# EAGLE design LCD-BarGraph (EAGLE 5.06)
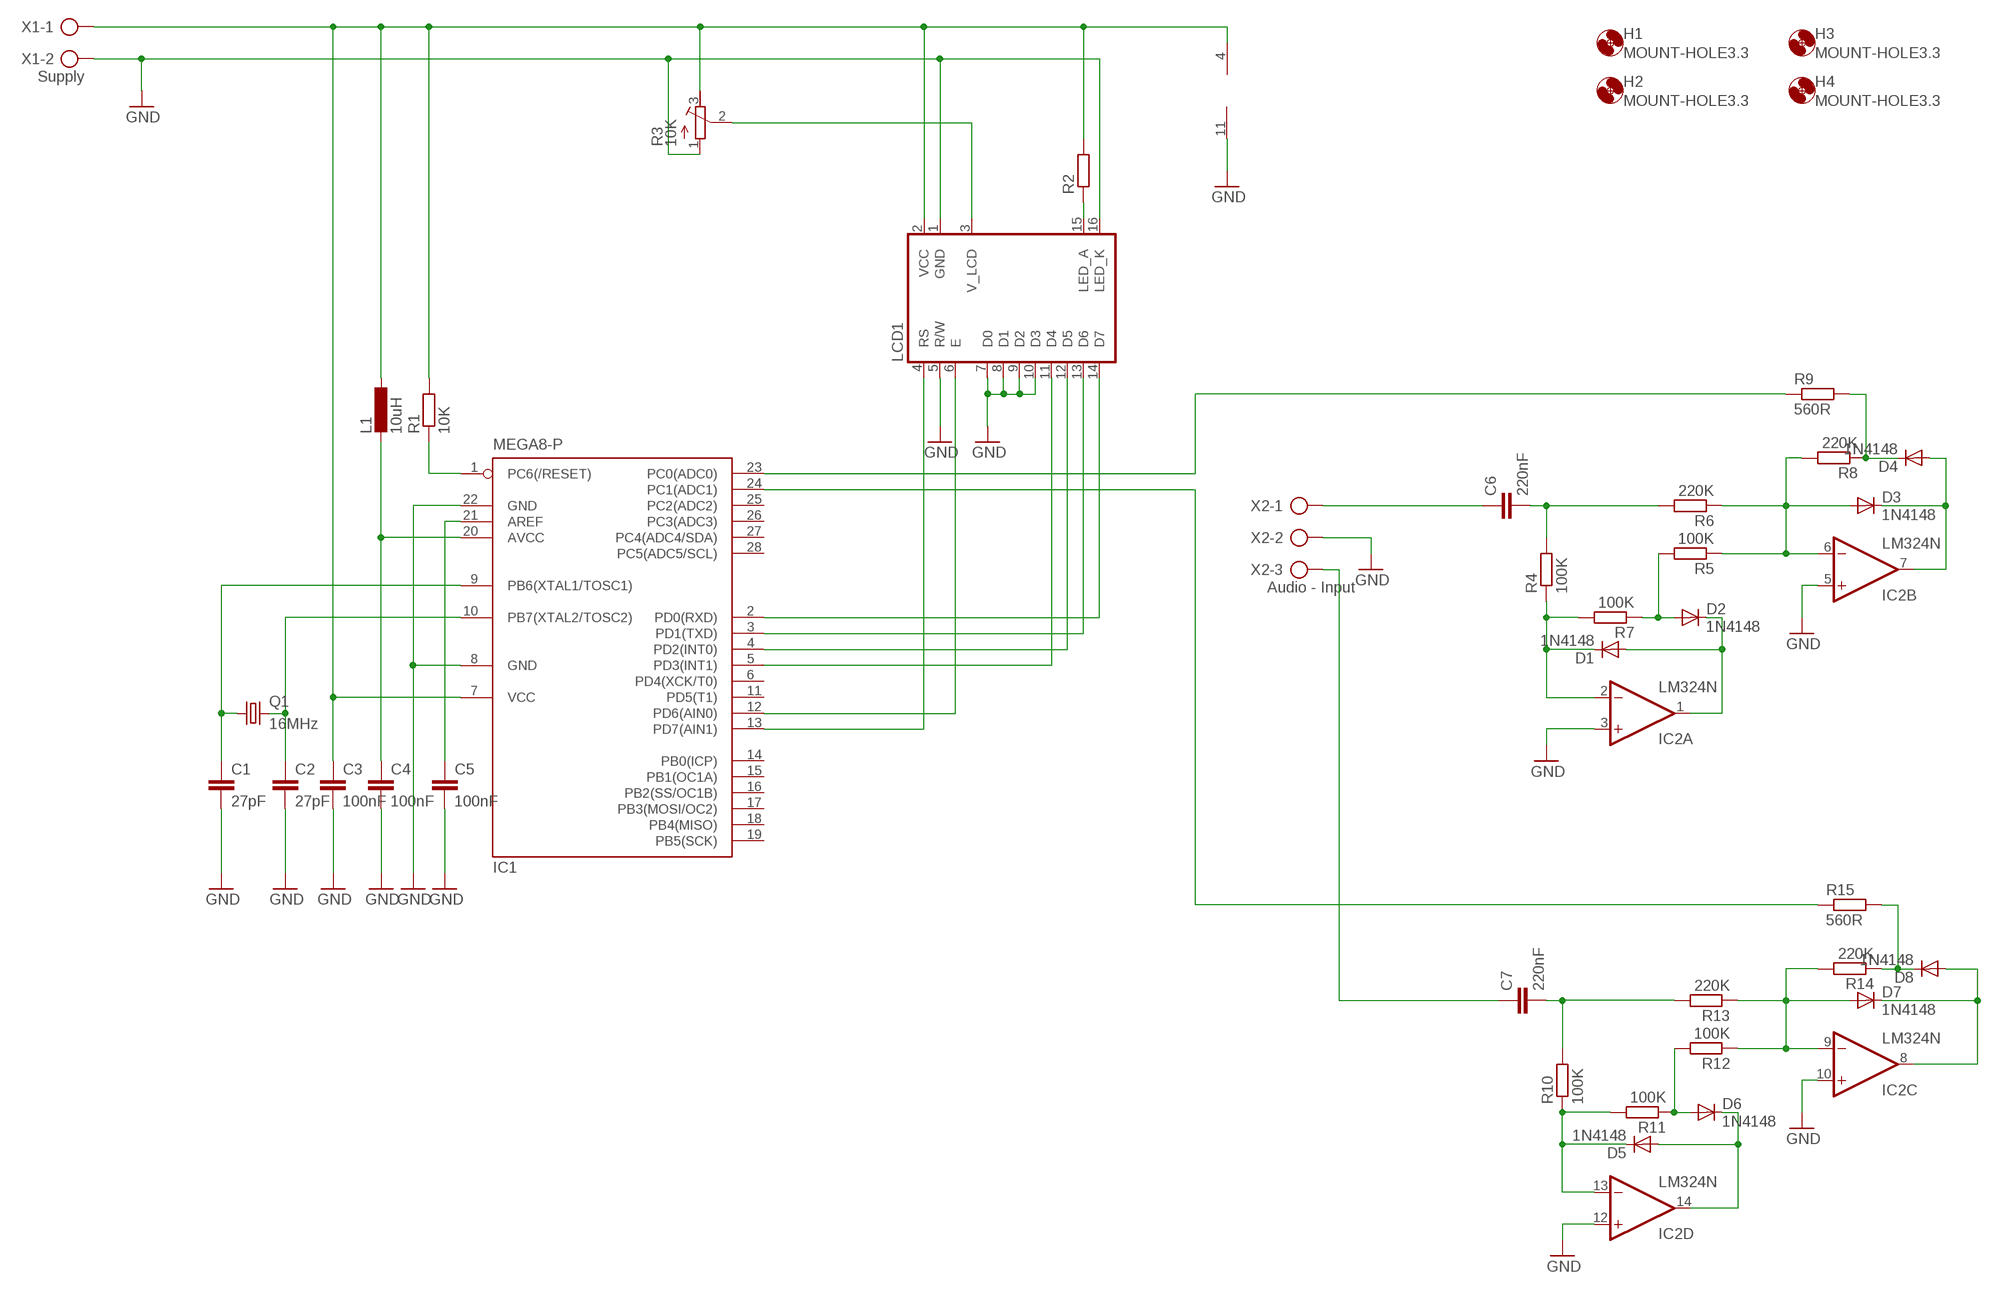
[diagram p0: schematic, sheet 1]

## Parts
C1  27pF  C-EU025-030X050  [C025-030X050]
C2  27pF  C-EU025-030X050  [C025-030X050]
C3  100nF  C-EU025-030X050  [C025-030X050]
C4  100nF  C-EU025-030X050  [C025-030X050]
C5  100nF  C-EU025-030X050  [C025-030X050]
C6  220nF  C-EU025-030X050  [C025-030X050]
C7  220nF  C-EU025-030X050  [C025-030X050]
D1  1N4148  1N4148DO35-7  [DO35-7]
D2  1N4148  1N4148DO35-7  [DO35-7]
D3  1N4148  1N4148DO35-7  [DO35-7]
D4  1N4148  1N4148DO35-7  [DO35-7]
D5  1N4148  1N4148DO35-7  [DO35-7]
D6  1N4148  1N4148DO35-7  [DO35-7]
D7  1N4148  1N4148DO35-7  [DO35-7]
D8  1N4148  1N4148DO35-7  [DO35-7]
H1  MOUNT-HOLE3.3  [3,3]
H2  MOUNT-HOLE3.3  [3,3]
H3  MOUNT-HOLE3.3  [3,3]
H4  MOUNT-HOLE3.3  [3,3]
IC1  MEGA8-P  [DIL28-3]
IC2  LM324N  [DIL14]
L1  10uH  L-MESC  [L-MESC]
LCD1  LCD-4X20  [LCD-4X20]
Q1  16MHz  CRYSTALHC49U-V  [HC49U-V]
R1  10K  R-EU_0207/10  [0207/10]
R2  R-EU_0207/10  [0207/10]
R3  10K  R-TRIMM64X  [RTRIM64X]
R4  100K  R-EU_0207/10  [0207/10]
R5  100K  R-EU_0207/10  [0207/10]
R6  220K  R-EU_0207/10  [0207/10]
R7  100K  R-EU_0207/10  [0207/10]
R8  220K  R-EU_0207/10  [0207/10]
R9  560R  R-EU_0207/10  [0207/10]
R10  100K  R-EU_0207/10  [0207/10]
R11  100K  R-EU_0207/10  [0207/10]
R12  100K  R-EU_0207/10  [0207/10]
R13  220K  R-EU_0207/10  [0207/10]
R14  220K  R-EU_0207/10  [0207/10]
R15  560R  R-EU_0207/10  [0207/10]
X1  Supply  AK300/2  [AK300/2]
X2  Audio - Input  AK300/3  [AK300/3]

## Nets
GND: C1.2 C2.2 C3.2 C4.2 C5.2 IC1.8(GND) IC1.22(GND) IC2.3(A:+IN) IC2.5(B:+IN) IC2.10(C:+IN) IC2.11(P:V-) IC2.12(D:+IN) LCD1.1(GND) LCD1.5(R/W) LCD1.7(D0) LCD1.8(D1) LCD1.9(D2) LCD1.10(D3) LCD1.16(LED_K) R3.1(E) X1.2 X2.2
N$1: C2.1 IC1.10(PB7(XTAL2/TOSC2)) Q1.2
N$2: C1.1 IC1.9(PB6(XTAL1/TOSC1)) Q1.1
N$3: C3.1 IC1.7(VCC) IC2.4(P:V+) L1.1 LCD1.2(VCC) R1.2 R2.2 R3.3(A) X1.1
N$4: C4.1 IC1.20(AVCC) L1.2
N$5: IC1.1(PC6(/RESET)) R1.1
N$6: LCD1.15(LED_A) R2.1
N$7: C5.1 IC1.21(AREF)
N$8: LCD1.3(V_LCD) R3.2(S)
N$9: C6.1 X2.1
N$10: C6.2 R4.2 R6.2
N$11: D1.C IC2.2(A:-IN) R4.1 R7.2
N$12: D1.A D2.C IC2.1(A:OUT)
N$13: D2.A R5.2 R7.1
N$14: D3.A IC2.6(B:-IN) R5.1 R6.1 R8.2
N$15: D3.C D4.A IC2.7(B:OUT)
N$16: D4.C R8.1 R9.2
N$17: C7.1 X2.3
N$18: C7.2 R10.2 R13.2
N$19: D5.C IC2.13(D:-IN) R10.1 R11.2
N$20: D6.A R11.1 R12.2
N$21: D5.A D6.C IC2.14(D:OUT)
N$22: D7.A IC2.9(C:-IN) R12.1 R13.1 R14.2
N$23: D7.C D8.A IC2.8(C:OUT)
N$24: D8.C R14.1 R15.2
N$25: IC1.23(PC0(ADC0)) R9.1
N$26: IC1.5(PD3(INT1)) LCD1.11(D4)
N$27: IC1.24(PC1(ADC1)) R15.1
N$28: IC1.4(PD2(INT0)) LCD1.12(D5)
N$29: IC1.3(PD1(TXD)) LCD1.13(D6)
N$30: IC1.2(PD0(RXD)) LCD1.14(D7)
N$31: IC1.12(PD6(AIN0)) LCD1.6(E)
N$32: IC1.13(PD7(AIN1)) LCD1.4(RS)
Unconnected: IC1.6(PD4(XCK/T0)) IC1.11(PD5(T1)) IC1.14(PB0(ICP)) IC1.15(PB1(OC1A)) IC1.16(PB2(SS/OC1B)) IC1.17(PB3(MOSI/OC2)) IC1.18(PB4(MISO)) IC1.19(PB5(SCK)) IC1.25(PC2(ADC2)) IC1.26(PC3(ADC3)) IC1.27(PC4(ADC4/SDA)) IC1.28(PC5(ADC5/SCL))

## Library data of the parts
C1-C7 = rcl:C-EU: CAPACITOR, European symbol
D1-D8 = diode:1N4148: DIODE
H1-H4 = holes:MOUNT-HOLE: MOUNTING HOLE with drill center marker
IC1 = atmel:MEGA8-P: MICROCONTROLLER 8 Kbytes FLASH, 1 kbytes SRAM, 512 bytes EEPROM, USART, 4-channel 10 bit ADC, 2-channel 8 bit ADC Pin compatible with Atmega48, ATMega88, ATMega168 Source: avr.lbr
IC2 = linear:LM324: OP AMP
L1 = oli:L-MESC: Medium Suppression Coil
LCD1 = oli:LCD-4X20: LCD 4 x 20 Characters
Q1 = crystal:CRYSTAL: CRYSTAL
R1 R2 R4-R15 = resistor:R-EU_: RESISTOR, European symbol
R3 = rcl:R-TRIMM: Trimm resistor
X1 = con-ptr500:AK300/2: CONNECTOR
X2 = con-ptr500:AK300/3: CONNECTOR

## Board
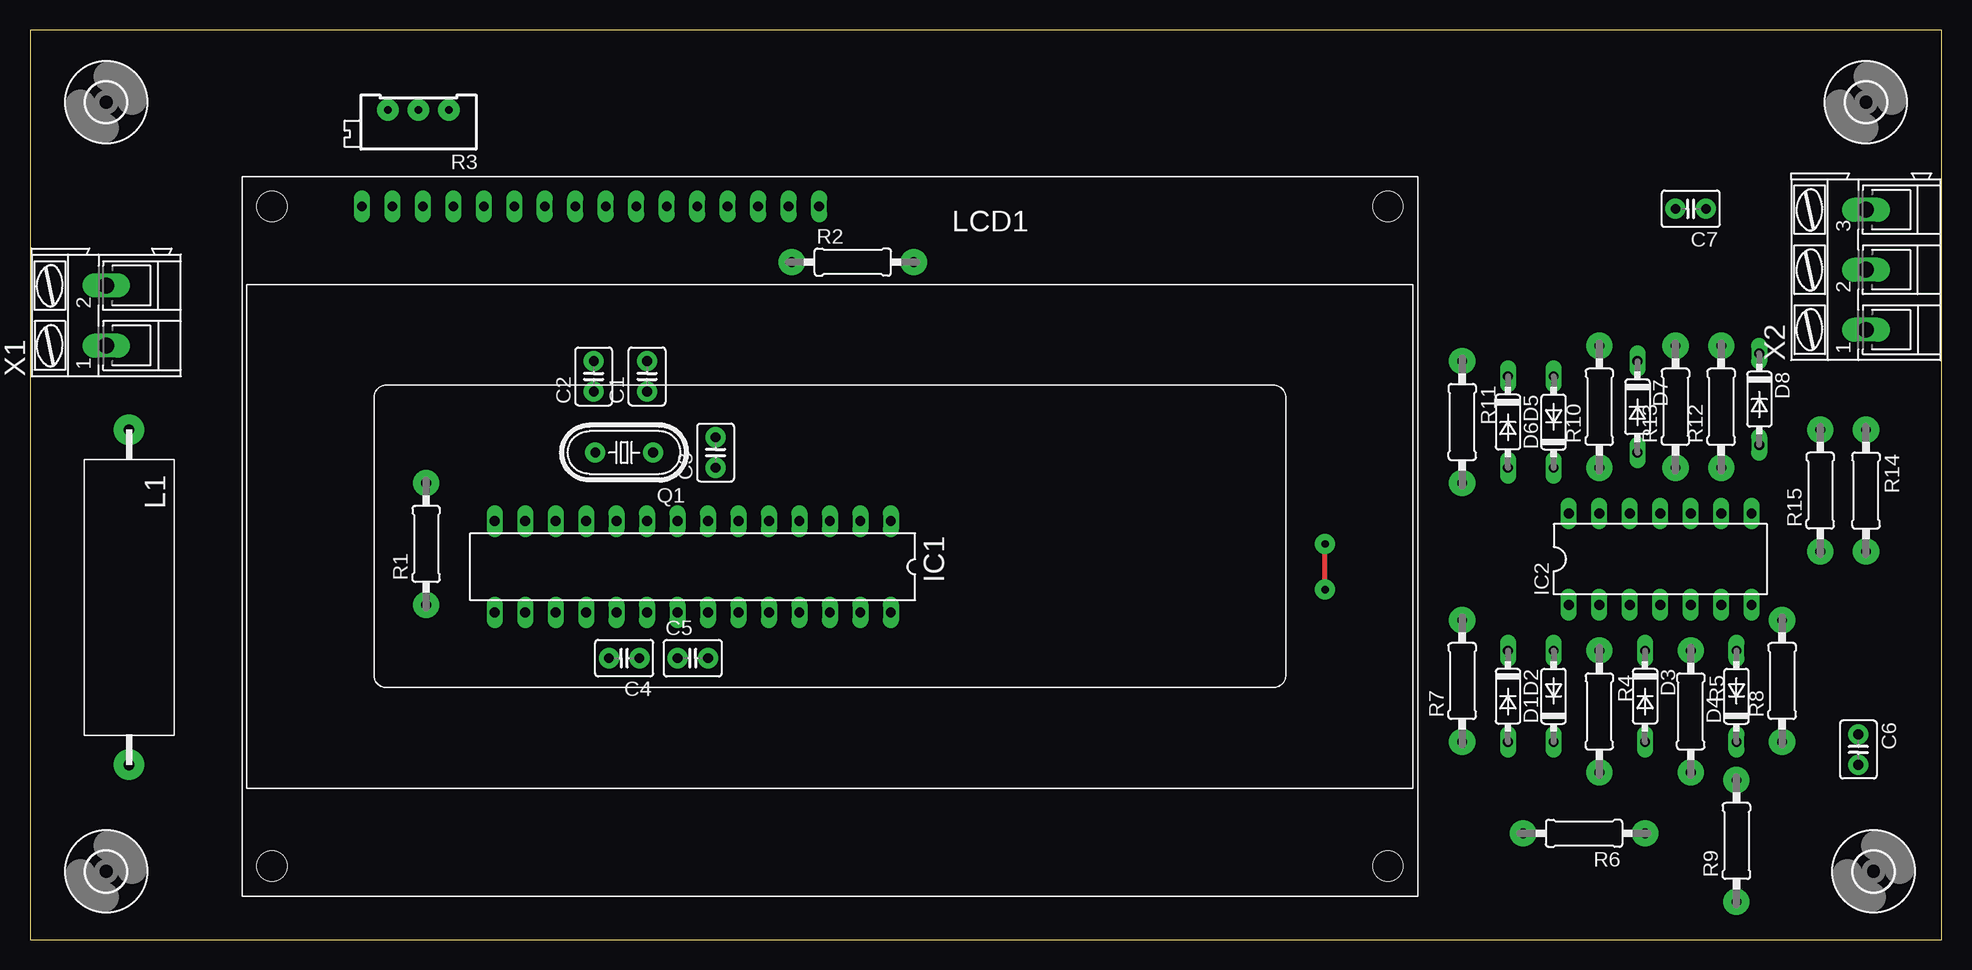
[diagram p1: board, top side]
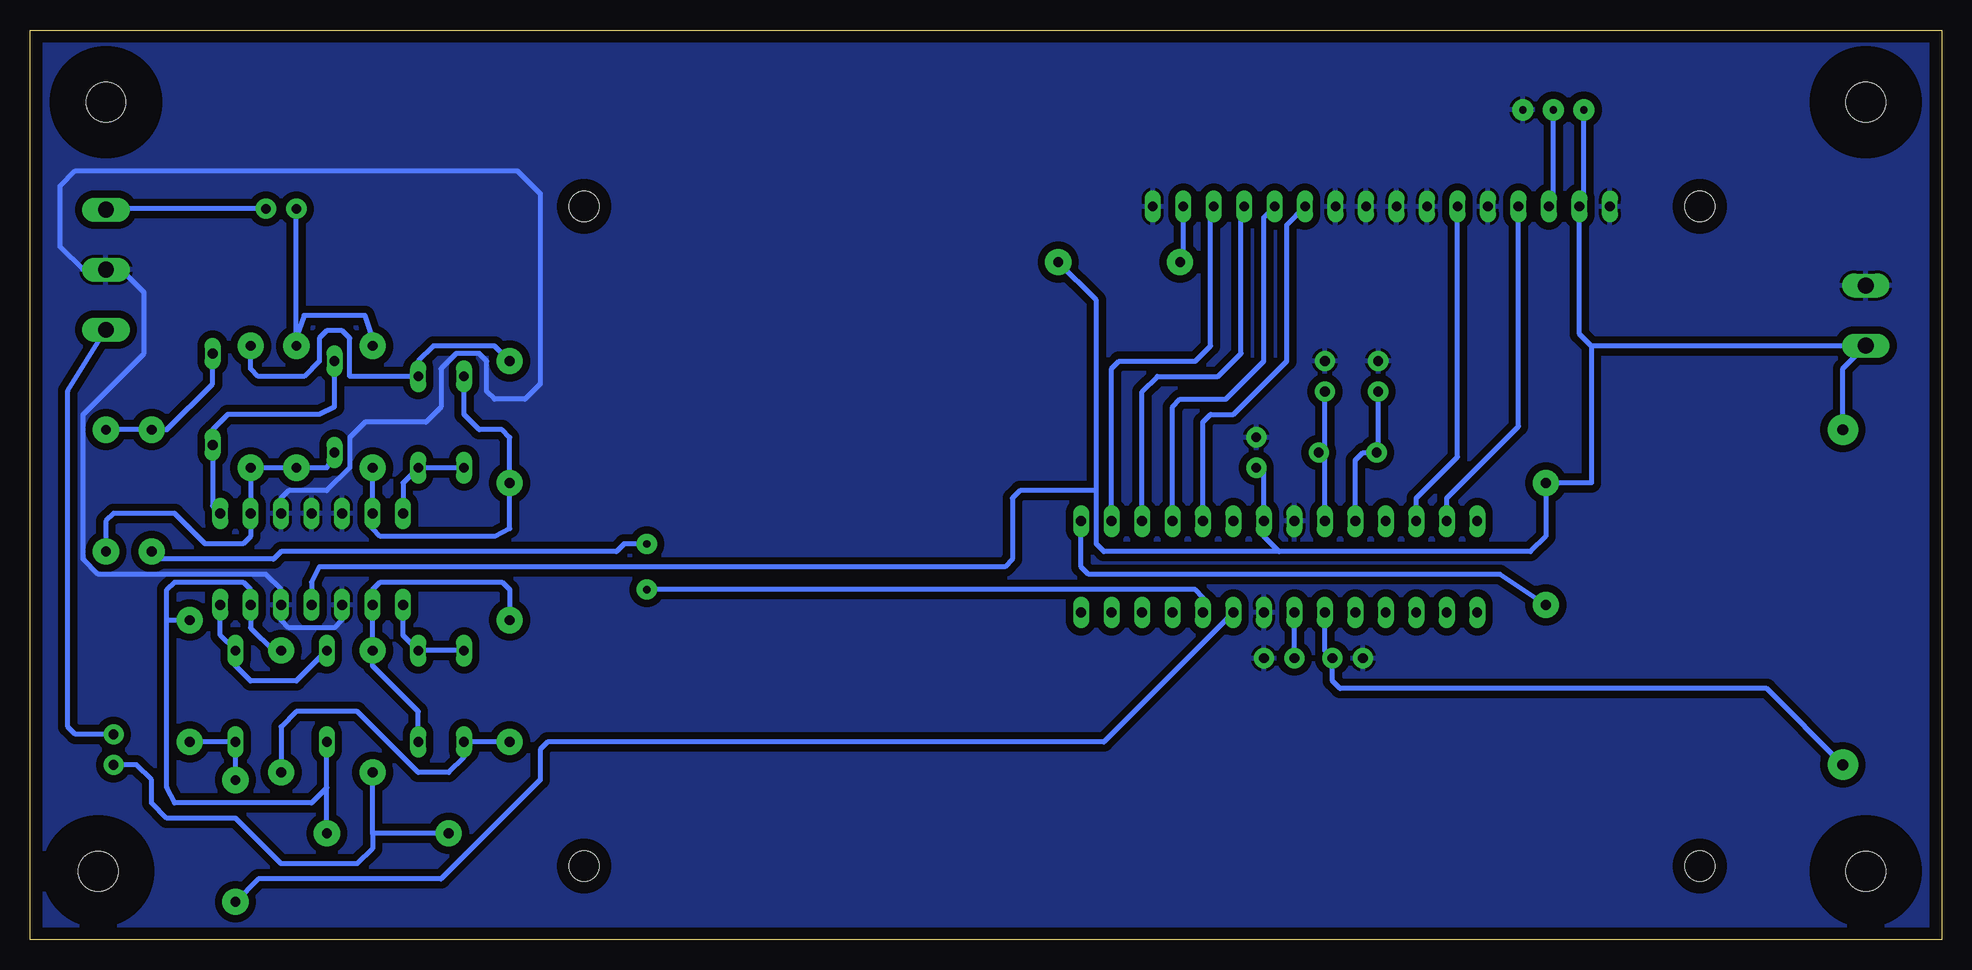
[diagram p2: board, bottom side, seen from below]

Size 159.37 x 75.87 mm. Coordinates in mm from the lower left corner, seen from the top.
Outline: 0,0 159.37,0 159.37,75.87 0,75.87 0,0
Copper layers (1*16): Top 0.035mm / dielectric 1.5mm / Bottom 0.035mm
Design rules "default": minimum track width 10mil, minimum drill 24mil, track to track 8mil, track to pad 8mil, pad to pad 8mil, via to via 8mil, smd to smd 8mil, copper to edge 40mil, drill to drill 8mil, minimum pad ring 10mil, minimum via ring 8mil, stop-mask expansion 4mil, vias tented up to drill 0mil, thermal gap 10mil

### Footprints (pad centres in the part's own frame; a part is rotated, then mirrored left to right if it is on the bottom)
C025-030X050 = drill 0.813 pad 1.676 round: 1 -1.27,0; 2 1.27,0
DO35-7 = drill 0.813 long: A 3.81,0; C -3.81,0
3,3 = hole 3.3: 0,0
DIL28-3 = drill 0.813 long: 1 -16.51,-3.81; 2 -13.97,-3.81; 3 -11.43,-3.81; 4 -8.89,-3.81; 5 -6.35,-3.81; 6 -3.81,-3.81; 7 -1.27,-3.81; 8 1.27,-3.81; 9 3.81,-3.81; 10 6.35,-3.81; 11 8.89,-3.81; 12 11.43,-3.81; 13 13.97,-3.81; 14 16.51,-3.81; 15 16.51,3.81; 16 13.97,3.81; 17 11.43,3.81; 18 8.89,3.81; 19 6.35,3.81; 20 3.81,3.81; 21 1.27,3.81; 22 -1.27,3.81; 23 -3.81,3.81; 24 -6.35,3.81; 25 -8.89,3.81; 26 -11.43,3.81; 27 -13.97,3.81; 28 -16.51,3.81
DIL14 = drill 0.813 long: 1 -7.62,-3.81; 2 -5.08,-3.81; 3 -2.54,-3.81; 4 0,-3.81; 5 2.54,-3.81; 6 5.08,-3.81; 7 7.62,-3.81; 8 7.62,3.81; 9 5.08,3.81; 10 2.54,3.81; 11 0,3.81; 12 -2.54,3.81; 13 -5.08,3.81; 14 -7.62,3.81
L-MESC = drill 0.9 pad 2.54 round: 1 -13.97,0; 2 13.97,0
LCD-4X20 = drill 0.813 long: 1 -39,27.5; 2 -36.46,27.5; 3 -33.92,27.5; 4 -31.38,27.5; 5 -28.84,27.5; 6 -26.3,27.5; 7 -23.76,27.5; 8 -21.22,27.5; 9 -18.68,27.5; 10 -16.14,27.5; 11 -13.6,27.5; 12 -11.06,27.5; 13 -8.52,27.5; 14 -5.98,27.5; 15 -3.44,27.5; 16 -0.9,27.5 | hole 2.5: -46.5,-27.5; -46.5,27.5; 46.5,27.5; 46.5,-27.5
HC49U-V = drill 0.813 pad 1.676 round: 1 -2.413,0; 2 2.413,0
0207/10 = drill 0.813 pad 2.184 round: 1 -5.08,0; 2 5.08,0
RTRIM64X = drill 0.61 pad 1.778 round: 1 1.27,-2.54; 2 1.27,0; 3 1.27,2.54
AK300/2 = drill 1.321 long: 1 -2.515,0; 2 2.489,0
AK300/3 = drill 1.321 long: 1 -5.004,0; 2 0,0; 3 5.004,0

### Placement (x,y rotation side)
C1  51.44,46.99 90 top
C2  46.99,46.99 90 top
C3  57.15,40.64 90 top
C4  49.53,23.5 180 top
C5  55.25,23.5 0 top
C6  152.4,15.88 270 top
C7  138.43,60.96 180 top
D1  127,20.32 90 top
D2  123.19,20.32 270 top
D3  134.62,20.32 270 top
D4  142.24,20.32 90 top
D5  123.19,43.18 270 top
D6  127,43.18 90 top
D7  133.99,44.45 270 top
D8  144.15,45.09 270 top
H1  6.35,5.71 0 top
H2  6.35,69.85 0 top
H3  153.03,69.85 0 top
H4  153.67,5.71 0 top
IC1  55.25,31.11 180 top
IC2  135.89,31.75 0 top
L1  8.25,28.57 270 top
LCD1  66.67,33.66 0 top
Q1  49.53,40.64 180 top
R1  33.02,33.02 90 top
R2  68.58,56.52 0 top
R3  32.39,67.94 90 top
R4  130.81,19.05 270 top
R5  138.43,19.05 270 top
R6  129.54,8.89 180 top
R7  119.38,21.59 90 top
R8  146.05,21.59 90 top
R9  142.24,8.26 90 top
R10  130.81,44.45 90 top
R11  119.38,43.18 270 top
R12  140.97,44.45 90 top
R13  137.16,44.45 90 top
R14  153.03,37.47 270 top
R15  149.22,37.47 90 top
X1  6.35,52.07 90 top
X2  153.03,55.88 90 top

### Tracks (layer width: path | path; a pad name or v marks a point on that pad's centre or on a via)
GND
  Bottom 0.406: IC2.3 133.35,26.67 133.99,26.04 137.8,26.04 138.43,26.67 IC2.5 138.43,29.21 139.7,30.48 153.67,30.48 154.94,31.75 154.94,43.81 149.86,48.9 149.86,53.98 151.77,55.88 X2.2 154.94,55.88 156.84,57.78 156.84,62.87 155.58,64.14 118.75,64.14 116.84,62.23 116.84,46.35 118.11,45.09 120.65,45.09 121.28,45.72 121.28,48.26 121.92,48.9 123.83,48.9 125.09,47.62 125.09,44.45 126.37,43.18 131.44,43.18 132.72,41.91 132.72,39.37 134.62,37.47 137.8,37.47 138.43,36.83 IC2.10
  pour Bottom (isolate 0.61): -0.63,76.2 159.38,76.2 160.02,0 0,0
N$1
  Bottom 0.406: IC1.10 48.89,40.01 48.26,40.64 Q1.2 46.99,40.77 C2.1
N$2
  Bottom 0.406: IC1.9 51.44,40.13 Q1.1 51.44,41.15 C1.1
N$3
  Bottom 0.406: IC2.4 135.89,29.84 135.25,31.11 78.11,31.11 77.47,31.75 77.47,36.83 76.84,37.47 70.48,37.47 | L1.1 8.25,47.65 X1.1 6.38,49.53 29.21,49.53 | 29.21,49.53 30.21,50.53 LCD1.2 29.85,61.52 R3.3 | C3.1 56.52,39.37 IC1.7 56.52,33.66 55.25,32.38 | 29.21,49.53 29.21,38.1 R1.2 33.02,33.66 34.29,32.38 55.25,32.38 | R2.2 70.48,53.34 70.48,37.47 | 70.48,37.47 70.48,33.02 69.85,32.38 55.25,32.38
N$4
  Bottom 0.406: IC1.20 51.44,24.13 C4.1 50.8,21.59 50.17,20.95 14.61,20.95 L1.2
N$5
  Bottom 0.406: R1.1 36.83,30.48 71.12,30.48 71.76,31.11 IC1.1
N$6
  Bottom 0.406: R2.1 63.23,56.78 LCD1.15
N$7
  Bottom 0.406: C5.1 IC1.21
N$8
  Bottom 0.406: LCD1.3 32.39,61.52 R3.2
N$9
  Bottom 0.406: X2.1 156.21,45.8 156.21,17.78 155.58,17.14 C6.1
N$10
  Bottom 0.406: 130.81,8.89 130.81,7.62 132.08,6.35 138.43,6.35 142.24,10.16 147.96,10.16 149.22,11.43 149.22,13.34 150.5,14.61 C6.2 | 130.81,8.89 R4.2 | R6.2 130.81,8.89
N$11
  Bottom 0.406: D1.C 127,19.05 130.81,22.86 R4.1 IC2.2 130.81,29.21 130.18,29.84 120.02,29.84 119.38,29.21 R7.2
N$12
  Bottom 0.406: IC2.1 128.27,25.4 D1.A D2.C
N$13
  Bottom 0.406: R7.1 D2.A 123.19,15.24 124.46,13.97 127,13.97 132.08,19.05 137.16,19.05 138.43,17.78 R5.2
N$14
  Bottom 0.406: R6.1 134.62,12.7 | R5.1 139.06,24.13 140.97,26.04 IC2.6 140.97,29.21 141.6,29.84 147.32,29.84 147.96,29.21 147.96,26.67 | 134.62,12.7 D3.A | 134.62,12.7 135.89,11.43 147.32,11.43 147.96,12.7 147.96,26.67 | 147.96,26.67 R8.2
N$15
  Bottom 0.406: D3.C 137.16,21.59 140.97,21.59 142.24,22.86 D4.A 143.51,25.4 IC2.7
N$16
  Bottom 0.406: R8.1 D4.C R9.2
N$17
  Bottom 0.406: X2.3 152.96,60.96 C7.1
N$18
  Bottom 0.406: R10.2 130.81,50.16 131.44,52.07 136.53,52.07 137.16,50.16 | 137.16,50.16 R13.2 | 137.16,50.16 C7.2
N$19
  Bottom 0.406: D5.C 123.19,43.81 121.92,42.55 120.02,42.55 119.38,41.91 R11.2 119.38,34.29 120.65,33.66 130.18,33.66 130.81,34.29 IC2.13 R10.1
N$20
  Bottom 0.406: R11.1 120.65,49.53 125.73,49.53 127,48.26 D6.A 132.72,46.99 132.72,50.16 133.35,50.8 134.62,50.8 135.25,50.16 135.25,48.26 136.53,46.99 140.34,46.99 140.97,47.62 R12.2
N$21
  Bottom 0.406: D5.A D6.C 128.27,38.1 IC2.14
N$22
  Bottom 0.406: D7.A 134.62,39.37 R13.1 R12.1 IC2.9 140.97,33.66 141.6,33.02 144.78,33.02 147.32,35.56 152.4,35.56 153.03,34.92 R14.2
N$23
  Bottom 0.406: IC2.8 144.15,36.2 D8.A 144.15,42.55 142.88,43.81 135.25,43.81 133.99,44.45 D7.C
N$24
  Bottom 0.406: R14.1 R15.2 147.96,42.55 144.15,46.35 D8.C
N$25
  Bottom 0.406: R9.1 140.34,5.08 125.09,5.08 116.84,13.34 116.84,15.88 116.2,16.51 69.85,16.51 IC1.23
N$26
  Bottom 0.406: LCD1.11 54.61,59.62 54.61,48.26 59.06,43.81 60.96,43.81 61.59,43.18 IC1.5
N$27  (via drill 0.6 pad 1.68)
  Top 0.406: v107.95,29.21 v107.95,33.02
  Bottom 0.406: R15.1 148.59,31.75 139.06,31.75 138.43,32.38 110.49,32.38 109.86,33.02 v107.95,33.02 | IC1.24 61.59,28.57 62.23,29.21 v107.95,29.21
N$28
  Bottom 0.406: LCD1.12 56.52,60.26 56.52,48.26 59.69,45.09 63.5,45.09 64.14,44.45 IC1.4
N$29
  Bottom 0.406: LCD1.13 58.42,60.89 58.42,48.9 60.33,46.99 65.41,46.99 66.67,45.72 IC1.3
N$30
  Bottom 0.406: LCD1.14 60.96,60.89 60.96,49.53 62.23,48.26 68.58,48.26 69.22,47.62 IC1.2
N$31
  Bottom 0.406: IC1.12 43.81,36.83 40.38,40.27 LCD1.6
N$32
  Bottom 0.406: IC1.13 41.28,36.83 35.3,42.81 LCD1.4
